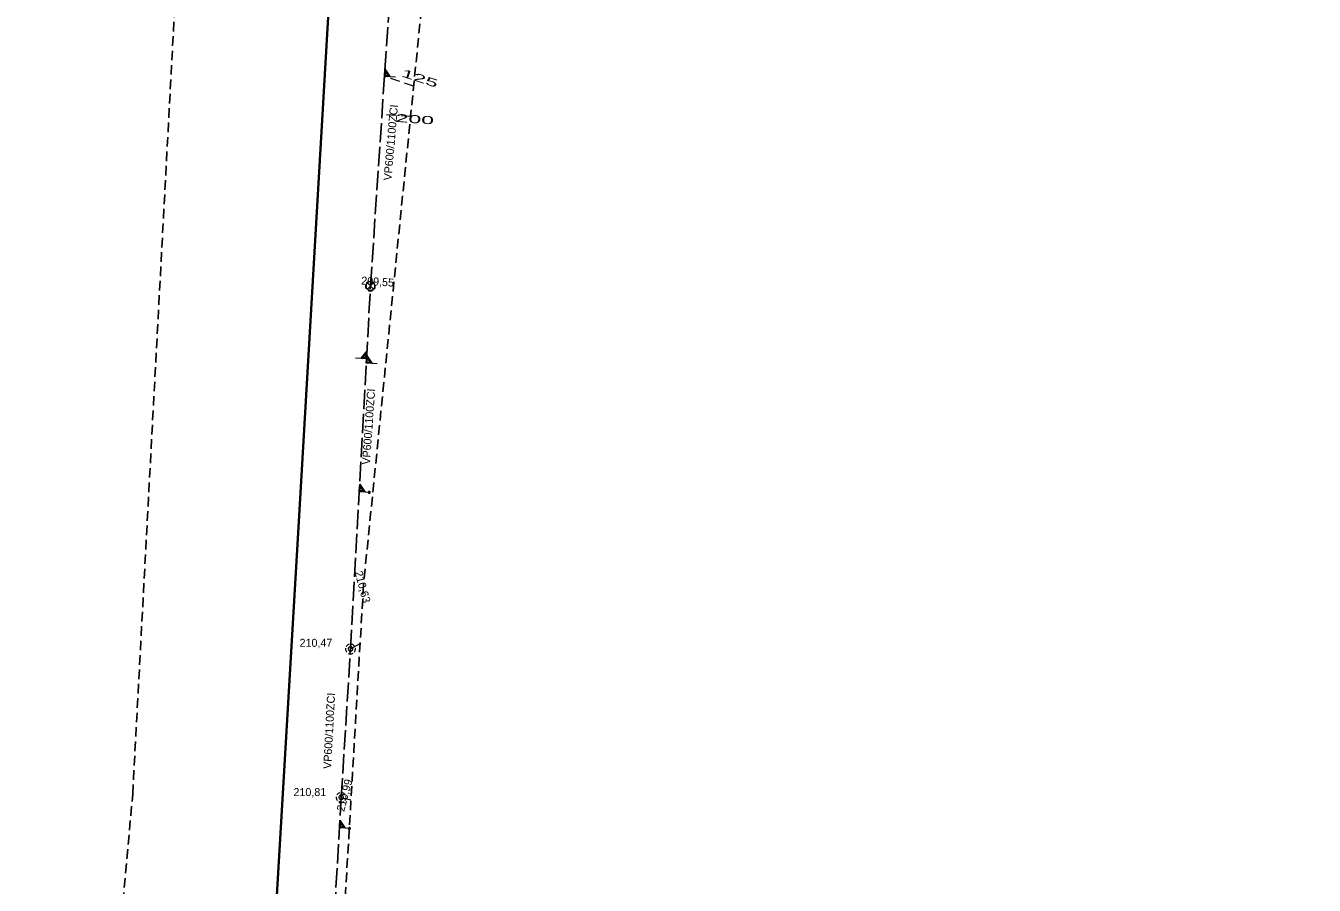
# Model space of a CAD drawing. Extents: x -744446 to -743929, y -1041261 to -1040599.
# Drawn here: x -744445.1 to -744316.3, y -1041089.2 to -1041003.3 of the extents above; entities that cross this region are included whole.
import ezdxf

# ---------------------------------------------------------------- set-up
doc = ezdxf.new("R2010")
doc.units = 0
doc.header["$LTSCALE"] = 0.32
doc.linetypes.add('LONG_DASHED', pattern=[7.5, 6, -1.5])
doc.linetypes.add('MEDIUM_DASHED', pattern=[4.5, 3, -1.5])
for name, color, linetype, lineweight in [('1', 7, 'MEDIUM_DASHED', 25), ('18', 7, 'Continuous', 13), ('20', 7, 'LONG_DASHED', 13), ('49', 7, 'MEDIUM_DASHED', 13)]:
    doc.layers.add(name, color=color, linetype=linetype, lineweight=lineweight)

msp = doc.modelspace()

# ---------------------------------------------------------------- linework, layer by layer
at = {"layer": '1'}
msp.add_lwpolyline([(-744438.077, -1041259.731), (-744438.679, -1041250.888), (-744445.125, -1041198.426), (-744434.434, -1041080.103), (-744426.87, -1040938.41), (-744425.446, -1040859.072), (-744414.192, -1040822.094), (-744390.076, -1040771.45), (-744357.118, -1040726.434), (-744307.278, -1040693.475), (-744241.36, -1040670.967), (-743937.498, -1040598.618), (-743928.655, -1040619.519), (-744129.684, -1040665.585), (-744218.109, -1040687.29), (-744311.358, -1040718.641), (-744361.198, -1040777.323), (-744391.745, -1040864.141), (-744411.355, -1041059.185), (-744416.379, -1041145.154), (-744432.569, -1041193.163), (-744432.047, -1041202.053), (-744422.803, -1041230.992), (-744424.813, -1041260.936)], close=True, dxfattribs=at)
at = {"layer": '18'}
for p, q in [((-744410.351, -1041029.629), (-744410.969, -1041029.011)), ((-744410.969, -1041029.629), (-744410.352, -1041029.012))]:
    msp.add_line(p, q, dxfattribs=at)
for points in [[(-744408.166, -1041008.462), (-744409.26, -1041008.388), (-744409.209, -1041007.62), (-744408.683, -1041008.427)], [(-744408.798, -1041008.369), (-744409.213, -1041008.342), (-744409.175, -1041007.777), (-744408.797, -1041008.369)], [(-744408.878, -1041008.317), (-744409.169, -1041008.297), (-744409.144, -1041007.926), (-744408.878, -1041008.318)], [(-744410.812, -1041028.858), (-744410.883, -1041028.886), (-744410.95, -1041028.925), (-744411.01, -1041028.973), (-744411.061, -1041029.03), (-744411.085, -1041029.064)], [(-744410.271, -1041029.041), (-744410.321, -1041028.983), (-744410.379, -1041028.933), (-744410.444, -1041028.892), (-744410.515, -1041028.863), (-744410.564, -1041028.849)], [(-744411.157, -1041029.25), (-744411.163, -1041029.327), (-744411.157, -1041029.404), (-744411.141, -1041029.479), (-744411.112, -1041029.55), (-744411.071, -1041029.616), (-744411.056, -1041029.638)], [(-744410.899, -1041029.767), (-744410.829, -1041029.798), (-744410.754, -1041029.817), (-744410.678, -1041029.824), (-744410.601, -1041029.819), (-744410.526, -1041029.802), (-744410.454, -1041029.774), (-744410.394, -1041029.739)], [(-744410.276, -1041029.627), (-744410.235, -1041029.562), (-744410.204, -1041029.492), (-744410.184, -1041029.417), (-744410.177, -1041029.341), (-744410.182, -1041029.264), (-744410.188, -1041029.229)], [(-744412.148, -1041036.516), (-744411.054, -1041036.576), (-744411.012, -1041035.806), (-744411.631, -1041036.544)], [(-744411.51, -1041036.5), (-744411.095, -1041036.522), (-744411.064, -1041035.958), (-744411.511, -1041036.499)], [(-744411.424, -1041036.457), (-744411.133, -1041036.473), (-744411.113, -1041036.103), (-744411.424, -1041036.458)], [(-744409.988, -1041037.099), (-744411.082, -1041037.038), (-744411.04, -1041036.27), (-744410.505, -1041037.07)], [(-744410.62, -1041037.014), (-744411.035, -1041036.991), (-744411.004, -1041036.426), (-744410.619, -1041037.014)], [(-744410.701, -1041036.962), (-744410.992, -1041036.946), (-744410.971, -1041036.575), (-744410.701, -1041036.963)], [(-744410.689, -1041049.941), (-744411.782, -1041049.881), (-744411.74, -1041049.112), (-744411.205, -1041049.912)], [(-744411.32, -1041049.856), (-744411.735, -1041049.833), (-744411.704, -1041049.268), (-744411.319, -1041049.856)], [(-744411.401, -1041049.804), (-744411.693, -1041049.788), (-744411.672, -1041049.417), (-744411.401, -1041049.805)], [(-744412.802, -1041065.124), (-744412.873, -1041065.152), (-744412.94, -1041065.191), (-744413, -1041065.239), (-744413.051, -1041065.296), (-744413.075, -1041065.33)], [(-744412.261, -1041065.307), (-744412.311, -1041065.249), (-744412.369, -1041065.199), (-744412.434, -1041065.158), (-744412.505, -1041065.129), (-744412.554, -1041065.115)], [(-744413.147, -1041065.516), (-744413.152, -1041065.593), (-744413.147, -1041065.67), (-744413.13, -1041065.745), (-744413.102, -1041065.816), (-744413.061, -1041065.882), (-744413.046, -1041065.904)], [(-744412.889, -1041066.033), (-744412.819, -1041066.064), (-744412.744, -1041066.083), (-744412.668, -1041066.09), (-744412.591, -1041066.085), (-744412.516, -1041066.068), (-744412.444, -1041066.04), (-744412.384, -1041066.005)], [(-744412.266, -1041065.893), (-744412.225, -1041065.828), (-744412.194, -1041065.758), (-744412.174, -1041065.683), (-744412.167, -1041065.607), (-744412.172, -1041065.53), (-744412.178, -1041065.495)], [(-744414.083, -1041080.349), (-744414.088, -1041080.426), (-744414.083, -1041080.503), (-744414.066, -1041080.578), (-744414.038, -1041080.649), (-744413.997, -1041080.715), (-744413.982, -1041080.737)], [(-744413.738, -1041079.957), (-744413.809, -1041079.985), (-744413.875, -1041080.024), (-744413.936, -1041080.072), (-744413.987, -1041080.129), (-744414.011, -1041080.163)], [(-744413.196, -1041080.14), (-744413.247, -1041080.082), (-744413.304, -1041080.032), (-744413.37, -1041079.991), (-744413.441, -1041079.962), (-744413.49, -1041079.948)], [(-744413.201, -1041080.726), (-744413.161, -1041080.661), (-744413.13, -1041080.591), (-744413.11, -1041080.516), (-744413.103, -1041080.44), (-744413.108, -1041080.363), (-744413.114, -1041080.328)], [(-744413.825, -1041080.866), (-744413.755, -1041080.897), (-744413.679, -1041080.916), (-744413.603, -1041080.923), (-744413.527, -1041080.918), (-744413.451, -1041080.901), (-744413.38, -1041080.873), (-744413.32, -1041080.838)], [(-744412.665, -1041083.529), (-744413.758, -1041083.465), (-744413.713, -1041082.696), (-744413.181, -1041083.499)], [(-744413.296, -1041083.442), (-744413.711, -1041083.417), (-744413.678, -1041082.852), (-744413.295, -1041083.442)], [(-744413.377, -1041083.39), (-744413.669, -1041083.373), (-744413.647, -1041083.001), (-744413.377, -1041083.391)]]:
    msp.add_lwpolyline(points, dxfattribs=at)
for points in [[(-744410.223, -1041029.321), (-744410.226, -1041029.275), (-744410.233, -1041029.23), (-744410.245, -1041029.186), (-744410.261, -1041029.143), (-744410.282, -1041029.102), (-744410.307, -1041029.064), (-744410.336, -1041029.028), (-744410.368, -1041028.996), (-744410.404, -1041028.967), (-744410.442, -1041028.942), (-744410.483, -1041028.922), (-744410.526, -1041028.905), (-744410.57, -1041028.893), (-744410.615, -1041028.886), (-744410.661, -1041028.884), (-744410.706, -1041028.886), (-744410.752, -1041028.893), (-744410.796, -1041028.905), (-744410.839, -1041028.922), (-744410.88, -1041028.942), (-744410.918, -1041028.967), (-744410.954, -1041028.996), (-744410.986, -1041029.028), (-744411.015, -1041029.064), (-744411.04, -1041029.103), (-744411.061, -1041029.143), (-744411.076, -1041029.186), (-744411.089, -1041029.23), (-744411.096, -1041029.275), (-744411.098, -1041029.321), (-744411.096, -1041029.367), (-744411.089, -1041029.412), (-744411.076, -1041029.456), (-744411.061, -1041029.499), (-744411.04, -1041029.54), (-744411.015, -1041029.578), (-744410.986, -1041029.614), (-744410.954, -1041029.646), (-744410.918, -1041029.675), (-744410.88, -1041029.7), (-744410.839, -1041029.721), (-744410.796, -1041029.737), (-744410.752, -1041029.749), (-744410.706, -1041029.756), (-744410.661, -1041029.759), (-744410.615, -1041029.756), (-744410.57, -1041029.749), (-744410.526, -1041029.737), (-744410.483, -1041029.721), (-744410.442, -1041029.7), (-744410.404, -1041029.675), (-744410.368, -1041029.646), (-744410.336, -1041029.614), (-744410.307, -1041029.578), (-744410.282, -1041029.54), (-744410.261, -1041029.499), (-744410.245, -1041029.456), (-744410.233, -1041029.412), (-744410.226, -1041029.367)], [(-744410.777, -1041049.842), (-744410.811, -1041049.846), (-744410.841, -1041049.861), (-744410.863, -1041049.886), (-744410.875, -1041049.918), (-744410.876, -1041049.951), (-744410.864, -1041049.982), (-744410.843, -1041050.008), (-744410.814, -1041050.025), (-744410.781, -1041050.03), (-744410.748, -1041050.024), (-744410.719, -1041050.006), (-744410.699, -1041049.979), (-744410.689, -1041049.948), (-744410.69, -1041049.914), (-744410.704, -1041049.883), (-744410.727, -1041049.86), (-744410.758, -1041049.845)], [(-744410.78, -1041049.869), (-744410.808, -1041049.873), (-744410.832, -1041049.888), (-744410.846, -1041049.912), (-744410.851, -1041049.94), (-744410.843, -1041049.967), (-744410.825, -1041049.988), (-744410.799, -1041050.001), (-744410.771, -1041050.001), (-744410.746, -1041049.991), (-744410.726, -1041049.97), (-744410.717, -1041049.943), (-744410.719, -1041049.915), (-744410.734, -1041049.89), (-744410.756, -1041049.874)], [(-744412.418, -1041065.576), (-744412.424, -1041065.524), (-744412.441, -1041065.474), (-744412.47, -1041065.43), (-744412.508, -1041065.393), (-744412.553, -1041065.366), (-744412.603, -1041065.35), (-744412.655, -1041065.345), (-744412.706, -1041065.352), (-744412.755, -1041065.371), (-744412.799, -1041065.401), (-744412.835, -1041065.44), (-744412.861, -1041065.485), (-744412.875, -1041065.536), (-744412.879, -1041065.588), (-744412.87, -1041065.64), (-744412.85, -1041065.688), (-744412.82, -1041065.731), (-744412.78, -1041065.766), (-744412.733, -1041065.79), (-744412.683, -1041065.804), (-744412.63, -1041065.806), (-744412.579, -1041065.796), (-744412.531, -1041065.774), (-744412.489, -1041065.742), (-744412.456, -1041065.702), (-744412.432, -1041065.655), (-744412.419, -1041065.604)], [(-744413.353, -1041080.409), (-744413.36, -1041080.357), (-744413.377, -1041080.307), (-744413.406, -1041080.263), (-744413.444, -1041080.226), (-744413.489, -1041080.199), (-744413.539, -1041080.183), (-744413.591, -1041080.178), (-744413.642, -1041080.185), (-744413.691, -1041080.204), (-744413.735, -1041080.234), (-744413.771, -1041080.273), (-744413.797, -1041080.318), (-744413.811, -1041080.369), (-744413.815, -1041080.421), (-744413.806, -1041080.473), (-744413.786, -1041080.521), (-744413.755, -1041080.564), (-744413.716, -1041080.599), (-744413.669, -1041080.623), (-744413.619, -1041080.637), (-744413.566, -1041080.639), (-744413.515, -1041080.629), (-744413.467, -1041080.607), (-744413.424, -1041080.575), (-744413.392, -1041080.535), (-744413.368, -1041080.488), (-744413.355, -1041080.437)], [(-744412.753, -1041083.429), (-744412.787, -1041083.433), (-744412.817, -1041083.449), (-744412.839, -1041083.473), (-744412.851, -1041083.505), (-744412.852, -1041083.538), (-744412.841, -1041083.57), (-744412.819, -1041083.596), (-744412.79, -1041083.613), (-744412.757, -1041083.617), (-744412.725, -1041083.611), (-744412.696, -1041083.594), (-744412.675, -1041083.567), (-744412.665, -1041083.536), (-744412.666, -1041083.502), (-744412.68, -1041083.471), (-744412.703, -1041083.447), (-744412.733, -1041083.433)], [(-744412.756, -1041083.456), (-744412.784, -1041083.461), (-744412.808, -1041083.475), (-744412.822, -1041083.499), (-744412.827, -1041083.527), (-744412.82, -1041083.555), (-744412.801, -1041083.576), (-744412.776, -1041083.588), (-744412.748, -1041083.589), (-744412.722, -1041083.578), (-744412.703, -1041083.558), (-744412.693, -1041083.531), (-744412.695, -1041083.503), (-744412.71, -1041083.478), (-744412.732, -1041083.462)]]:
    msp.add_lwpolyline(points, close=True, dxfattribs=at)
at = {"layer": '20', "lineweight": 25}
msp.add_line((-744410.659, -1041029.321), (-744408.243, -1040993.153), dxfattribs=at)
at = {"layer": '20'}
for p, q in [((-744412.649, -1041065.587), (-744411.698, -1041065.057)), ((-744413.585, -1041080.42), (-744412.61, -1041080.648))]:
    msp.add_line(p, q, dxfattribs=at)
at = {"layer": '20', "linetype": 'Continuous', "lineweight": 35}
msp.add_lwpolyline([(-744429.62, -1041252.21), (-744428.789, -1041237.94), (-744437.959, -1041195.193), (-744423.3, -1041145.69), (-744417.879, -1041053.98), (-744409.949, -1040917.67), (-744407.76, -1040880.01), (-744407.219, -1040869.23), (-744404.395, -1040847.829), (-744400.25, -1040827.35), (-744393.491, -1040807.621), (-744384.879, -1040787.9), (-744372.238, -1040768.547), (-744361.26, -1040752.62), (-744345.317, -1040736.555), (-744330.739, -1040723.14), (-744312.333, -1040710.859), (-744294.67, -1040700.75), (-744274.728, -1040692.583), (-744254.699, -1040686.49), (-744133.87, -1040657.39), (-743953.289, -1040613.85), (-743946.017, -1040612.141)], dxfattribs=at)
at = {"layer": '20', "lineweight": 25}
for points in [[(-744413.585, -1041080.42), (-744412.649, -1041065.587), (-744410.659, -1041029.321)], [(-744417.433, -1041148.278), (-744416.493, -1041130.146), (-744413.585, -1041080.42)]]:
    msp.add_lwpolyline(points, dxfattribs=at)
at = {"layer": '49'}
for p, q in [((-744406.345, -1041009.348), (-744409.26, -1041008.389)), ((-744406.649, -1041012.372), (-744409.514, -1041012.189))]:
    msp.add_line(p, q, dxfattribs=at)

# ---------------------------------------------------------------- texts
at = {"layer": '1'}
for s, rotation, width, p in [('125 ', 342, 2.1, (-744407.631, -1041008.367)), ('200 ', 356, 2.15, (-744408.165, -1041012.917))]:
    msp.add_text(s, height=0.8, rotation=rotation, dxfattribs=dict(at, width=width)).set_placement(p)
for s, rotation, p in [('VP600/1100ZCI ', 85, (-744408.565, -1041018.809)), ('209,55', 356, (-744411.605, -1041029.169)), ('VP600/1100ZCI ', 86, (-744410.716, -1041047.197)), ('210,63', 285, (-744412.251, -1041057.905)), ('VP600/1100ZCI ', 87, (-744414.591, -1041077.588)), ('210,99', 75, (-744413.298, -1041081.886))]:
    msp.add_text(s, height=0.8, rotation=rotation, dxfattribs=at).set_placement(p)
for s, p in [('210,47', (-744417.747, -1041065.375)), ('210,81', (-744418.357, -1041080.288))]:
    msp.add_text(s, height=0.8, dxfattribs=at).set_placement(p)

doc.saveas('drawing.dxf')
